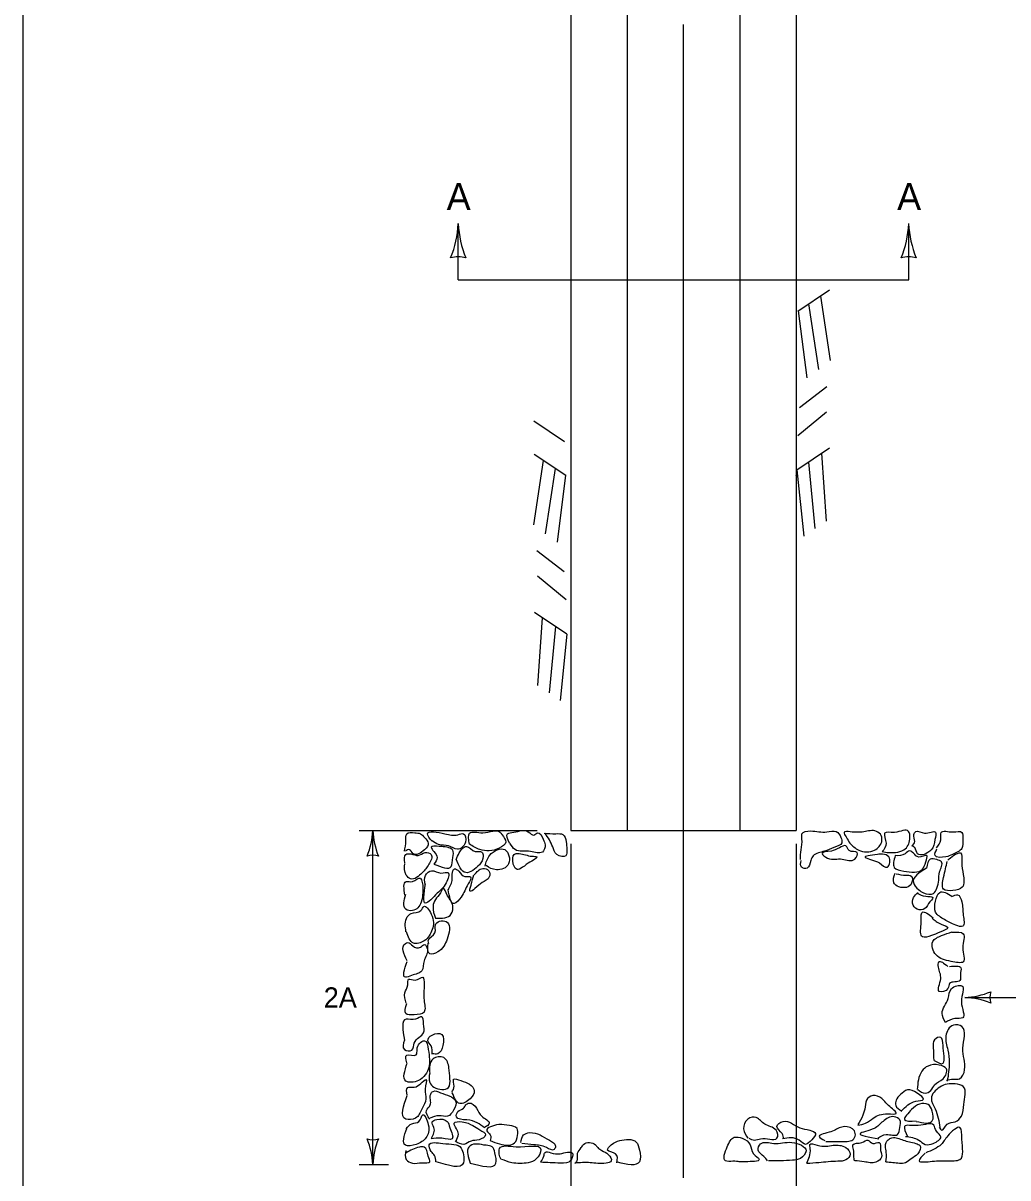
# Model space of a CAD drawing. Extents: x 49991.4 to 50021, y 49987.6 to 50011.4.
# Drawn here: x 50008.067 to 50010.982, y 49993.01 to 49996.429 of the extents above; entities that cross this region are included whole.
import ezdxf

# ---------------------------------------------------------------- set-up
doc = ezdxf.new("R2010")
doc.units = 0
for name, color, linetype in [('Level 1', 7, 'Continuous'), ('Level 2', 7, 'Continuous'), ('Level 3', 7, 'Continuous'), ('Level 6', 7, 'Continuous')]:
    doc.layers.add(name, color=color, linetype=linetype)

msp = doc.modelspace()

# ---------------------------------------------------------------- linework, layer by layer
at = {"layer": 'Level 1'}
for p, q in [((50008.0668, 49990.5622), (50008.0668, 49998.9992)), ((50009.8552, 49997.6503), (50009.8552, 49994.0392)), ((50010.1886, 49997.6503), (50010.1886, 49994.0392)), ((50009.6885, 49997.2058), (50009.6885, 49994.0392)), ((50010.3553, 49997.2058), (50010.3553, 49994.0392)), ((50010.3607, 49995.5769), (50010.4547, 49995.6394)), ((50010.4276, 49995.6214), (50010.4566, 49995.4306)), ((50010.3923, 49995.598), (50010.4218, 49995.4042)), ((50010.3619, 49995.5777), (50010.3872, 49995.3793)), ((50010.3655, 49995.2916), (50010.4466, 49995.3536)), ((50010.3603, 49995.2086), (50010.445, 49995.2788)), ((50009.6701, 49995.1899), (50009.5787, 49995.2511)), ((50009.6739, 49995.09), (50009.5799, 49995.1525)), ((50010.3577, 49995.107), (50010.4541, 49995.1716)), ((50010.4305, 49995.1558), (50010.4444, 49994.9551)), ((50009.6069, 49995.1345), (50009.578, 49994.9438)), ((50009.6422, 49995.111), (50009.6128, 49994.9174)), ((50010.3577, 49995.107), (50010.3781, 49994.9107)), ((50010.3918, 49995.1298), (50010.4107, 49994.933)), ((50009.6728, 49995.0907), (50009.6475, 49994.8924)), ((50009.6691, 49994.8047), (50009.5881, 49994.8668)), ((50009.6743, 49994.7218), (50009.5896, 49994.7919)), ((50009.6768, 49994.6201), (50009.5805, 49994.6847)), ((50009.604, 49994.6689), (50009.5902, 49994.4682)), ((50009.6427, 49994.6429), (50009.6239, 49994.4462)), ((50009.6768, 49994.6201), (50009.6565, 49994.4238)), ((50009.6885, 49994.0392), (50010.3553, 49994.0392))]:
    msp.add_line(p, q, dxfattribs=at)
msp.add_lwpolyline([(50010.3553, 49995.0904), (50010.3537, 49995.089)], dxfattribs=at)
for points in [[(50009.3874, 49994.0005), (50009.3888, 49994.0311), (50009.4277, 49994.0325), (50009.4791, 49994.0339), (50009.4846, 49994.0269), (50009.4957, 49994.0047), (50009.4763, 49993.9866), (50009.4193, 49993.9825), (50009.3874, 49993.9991)], [(50010.6106, 49993.9765), (50010.6217, 49994.0015), (50010.6175, 49994.0307), (50010.6467, 49994.0335), (50010.6884, 49994.0363), (50010.6925, 49994.0182), (50010.6787, 49993.9849), (50010.63, 49993.9738), (50010.6106, 49993.9765)], [(50009.1957, 49993.978), (50009.1998, 49994.0086), (50009.2026, 49994.0294), (50009.2262, 49994.0322), (50009.2429, 49994.0294), (50009.2554, 49994.0183), (50009.2665, 49994.0016), (50009.2554, 49993.9821), (50009.2207, 49993.971), (50009.211, 49993.9821), (50009.1985, 49993.978)], [(50009.2776, 49994.0072), (50009.2637, 49994.0294), (50009.3151, 49994.0294), (50009.354, 49994.0266), (50009.3707, 49994.0294), (50009.3763, 49994.0044), (50009.3526, 49993.9835), (50009.3263, 49993.9933), (50009.2971, 49993.9974), (50009.2776, 49994.0086)], [(50009.5069, 49994.0017), (50009.5013, 49994.0295), (50009.5194, 49994.0337), (50009.5624, 49994.0351), (50009.5791, 49994.0254), (50009.5902, 49994.0323), (50009.6069, 49994.0129), (50009.6124, 49993.9962), (50009.6041, 49993.9753), (50009.5694, 49993.9767), (50009.5235, 49993.9823), (50009.5082, 49994.0017)], [(50009.6097, 49994.0309), (50009.6444, 49994.0295), (50009.6652, 49994.0267), (50009.6749, 49994.0059), (50009.6763, 49993.9823), (50009.6736, 49993.9642), (50009.6472, 49993.9684), (50009.6347, 49993.9906), (50009.6249, 49994.0115), (50009.6124, 49994.0309)], [(50010.3685, 49993.9527), (50010.3699, 49993.9819), (50010.3727, 49994.0139), (50010.3727, 49994.0291), (50010.3977, 49994.0375), (50010.4463, 49994.0347), (50010.4741, 49994.0361), (50010.488, 49994.018), (50010.4907, 49994.0027), (50010.4671, 49993.9888), (50010.4393, 49993.9777), (50010.406, 49993.9638), (50010.399, 49993.95), (50010.3879, 49993.9277), (50010.3713, 49993.9305), (50010.3699, 49993.95)], [(50010.5142, 49994.0018), (50010.5031, 49994.0198), (50010.4976, 49994.0337), (50010.5156, 49994.0351), (50010.5559, 49994.0351), (50010.5934, 49994.0365), (50010.6073, 49994.024), (50010.6087, 49994.0059), (50010.5879, 49993.9809), (50010.5407, 49993.9809), (50010.5142, 49994.0018)], [(50010.6984, 49993.9925), (50010.7067, 49994.0064), (50010.704, 49994.0272), (50010.7095, 49994.0356), (50010.7359, 49994.0314), (50010.7678, 49994.0342), (50010.7665, 49994.012), (50010.7553, 49993.9814), (50010.7151, 49993.9703), (50010.7067, 49993.9883), (50010.6984, 49993.9939)], [(50010.771, 49993.9874), (50010.7836, 49994.0111), (50010.7849, 49994.0333), (50010.8197, 49994.0347), (50010.8461, 49994.0333), (50010.8488, 49994.0139), (50010.8461, 49993.9861), (50010.8183, 49993.968), (50010.7988, 49993.9611), (50010.7669, 49993.9652), (50010.7724, 49993.9847)], [(50009.2832, 49993.9392), (50009.2929, 49993.9587), (50009.2832, 49993.9767), (50009.2749, 49993.9892), (50009.2985, 49993.992), (50009.3221, 49993.9892), (50009.3388, 49993.9809), (50009.3388, 49993.9587), (50009.3346, 49993.9323), (50009.2832, 49993.9392)], [(50009.3485, 49993.9531), (50009.3582, 49993.9726), (50009.3666, 49993.9851), (50009.3791, 49993.992), (50009.4054, 49993.9767), (50009.4249, 49993.9753), (50009.4291, 49993.9628), (50009.4179, 49993.9378), (50009.3777, 49993.9142), (50009.3485, 49993.9545)], [(50009.4346, 49993.9337), (50009.4485, 49993.9656), (50009.493, 49993.9823), (50009.5041, 49993.9406), (50009.468, 49993.9225), (50009.4374, 49993.9351)], [(50010.4599, 49993.978), (50010.4835, 49993.9877), (50010.5029, 49993.9932), (50010.5126, 49993.9794), (50010.5363, 49993.9738), (50010.5293, 49993.9544), (50010.4918, 49993.9544), (50010.4488, 49993.9571), (50010.4321, 49993.971), (50010.4599, 49993.978)], [(50010.6489, 49993.9645), (50010.6781, 49993.9701), (50010.6919, 49993.9784), (50010.7031, 49993.9715), (50010.7183, 49993.9604), (50010.742, 49993.9645), (50010.7392, 49993.9465), (50010.7295, 49993.9243), (50010.6739, 49993.9187), (50010.6461, 49993.9298), (50010.6489, 49993.9645)], [(50009.1971, 49993.9431), (50009.1998, 49993.9681), (50009.2151, 49993.9695), (50009.236, 49993.9653), (50009.2568, 49993.9736), (50009.2749, 49993.9681), (50009.2679, 49993.9389), (50009.2485, 49993.9139), (50009.2137, 49993.8958), (50009.2012, 49993.907), (50009.1971, 49993.9417)], [(50009.518, 49993.9406), (50009.5207, 49993.9684), (50009.5541, 49993.967), (50009.5735, 49993.9628), (50009.5874, 49993.9614), (50009.5624, 49993.942), (50009.5263, 49993.9253), (50009.518, 49993.9392)], [(50010.5963, 49993.9678), (50010.6116, 49993.9692), (50010.6297, 49993.9609), (50010.6324, 49993.9442), (50010.6255, 49993.9303), (50010.6019, 49993.9428), (50010.5783, 49993.9525), (50010.5602, 49993.9595), (50010.5963, 49993.9678)], [(50010.7414, 49993.9278), (50010.7525, 49993.9542), (50010.7719, 49993.9528), (50010.7858, 49993.9459), (50010.7803, 49993.9167), (50010.7775, 49993.8917), (50010.7719, 49993.8681), (50010.7622, 49993.8528), (50010.733, 49993.8542), (50010.7177, 49993.8639), (50010.7025, 49993.8848), (50010.7414, 49993.9278)], [(50010.8044, 49993.9516), (50010.8224, 49993.9655), (50010.8419, 49993.9724), (50010.8461, 49993.946), (50010.8502, 49993.9085), (50010.8474, 49993.871), (50010.8197, 49993.8613), (50010.7919, 49993.8655), (50010.7919, 49993.9002), (50010.803, 49993.9474)], [(50009.2568, 49993.8795), (50009.2582, 49993.9059), (50009.2762, 49993.9198), (50009.304, 49993.9128), (50009.3249, 49993.9142), (50009.3193, 49993.8837), (50009.2929, 49993.8531), (50009.2582, 49993.8239), (50009.2582, 49993.8809)], [(50009.3249, 49993.8628), (50009.3374, 49993.8948), (50009.3374, 49993.91), (50009.3443, 49993.9253), (50009.3568, 49993.9184), (50009.3749, 49993.9031), (50009.3916, 49993.9017), (50009.3846, 49993.8809), (50009.3638, 49993.842), (50009.3429, 49993.8225), (50009.3249, 49993.8642)], [(50009.4027, 49993.9073), (50009.4277, 49993.9267), (50009.4457, 49993.9198), (50009.4471, 49993.9017), (50009.4263, 49993.885), (50009.4041, 49993.867), (50009.3902, 49993.8587), (50009.3929, 49993.8767), (50009.4013, 49993.9073)], [(50010.6516, 49993.9109), (50010.6807, 49993.9067), (50010.696, 49993.9039), (50010.6974, 49993.8831), (50010.6821, 49993.8706), (50010.6446, 49993.8845), (50010.6488, 49993.9123)], [(50009.1971, 49993.8475), (50009.2012, 49993.8878), (50009.2193, 49993.8878), (50009.2429, 49993.8975), (50009.2485, 49993.885), (50009.2499, 49993.8545), (50009.2457, 49993.8267), (50009.2193, 49993.8017), (50009.1998, 49993.8059), (50009.1998, 49993.8503)], [(50009.2874, 49993.7793), (50009.2804, 49993.814), (50009.2874, 49993.8349), (50009.3026, 49993.8543), (50009.3096, 49993.8682), (50009.3235, 49993.846), (50009.3388, 49993.8168), (50009.3346, 49993.7918), (50009.2874, 49993.7793)], [(50010.7141, 49993.853), (50010.7391, 49993.8446), (50010.7599, 49993.8404), (50010.7474, 49993.8224), (50010.7405, 49993.8113), (50010.7196, 49993.8043), (50010.7016, 49993.8182), (50010.703, 49993.8404), (50010.7169, 49993.8557)], [(50010.8169, 49993.8432), (50010.8336, 49993.8488), (50010.8461, 49993.8279), (50010.8502, 49993.7877), (50010.8488, 49993.7557), (50010.828, 49993.7585), (50010.7947, 49993.7752), (50010.7683, 49993.7974), (50010.7683, 49993.8293), (50010.7808, 49993.8557), (50010.8169, 49993.8446)], [(50009.2002, 49993.7387), (50009.2043, 49993.7832), (50009.2155, 49993.7929), (50009.2446, 49993.8026), (50009.253, 49993.8137), (50009.2752, 49993.7915), (50009.278, 49993.7456), (50009.2543, 49993.7123), (50009.2224, 49993.7054), (50009.2016, 49993.7387)], [(50009.2679, 49993.7043), (50009.2665, 49993.7126), (50009.286, 49993.7362), (50009.2888, 49993.7626), (50009.3235, 49993.7668), (50009.329, 49993.746), (50009.3221, 49993.7168), (50009.2943, 49993.6793), (50009.2707, 49993.6737), (50009.2665, 49993.7057)], [(50010.7585, 49993.7793), (50010.7849, 49993.7612), (50010.8044, 49993.7515), (50010.7808, 49993.7376), (50010.7558, 49993.7279), (50010.7294, 49993.7237), (50010.7252, 49993.7612), (50010.7294, 49993.7974), (50010.7613, 49993.7807)], [(50010.8169, 49993.7376), (50010.8502, 49993.7335), (50010.8488, 49993.6918), (50010.8502, 49993.6501), (50010.8141, 49993.6515), (50010.7696, 49993.6709), (50010.7599, 49993.7099), (50010.7863, 49993.7279), (50010.8169, 49993.739)], [(50009.204, 49993.6529), (50009.1985, 49993.7043), (50009.2054, 49993.7071), (50009.2207, 49993.6974), (50009.2429, 49993.6932), (50009.2554, 49993.7015), (50009.2637, 49993.6876), (50009.254, 49993.6529), (50009.2471, 49993.6237), (50009.2165, 49993.6098), (50009.1985, 49993.6043), (50009.204, 49993.6515)], [(50010.8099, 49993.6362), (50010.8433, 49993.6321), (50010.8419, 49993.6126), (50010.8405, 49993.5945), (50010.8099, 49993.5862), (50010.8044, 49993.5709), (50010.7794, 49993.5626), (50010.7836, 49993.6001), (50010.7766, 49993.6348), (50010.778, 49993.6501), (50010.8044, 49993.6362)], [(50009.2012, 49993.5279), (50009.1971, 49993.5584), (50009.2054, 49993.582), (50009.2082, 49993.5987), (50009.2276, 49993.5959), (50009.2499, 49993.6043), (50009.254, 49993.5848), (50009.254, 49993.5362), (50009.254, 49993.5015), (50009.2249, 49993.4931), (50009.1998, 49993.4973), (50009.2026, 49993.5265)], [(50010.7974, 49993.4709), (50010.8252, 49993.482), (50010.8488, 49993.4848), (50010.8447, 49993.532), (50010.8461, 49993.5793), (50010.8155, 49993.5709), (50010.8058, 49993.5418), (50010.7877, 49993.4973), (50010.7974, 49993.4709)], [(50009.1957, 49993.4181), (50009.2012, 49993.4806), (50009.229, 49993.4806), (50009.2471, 49993.4876), (50009.2526, 49993.4667), (50009.2526, 49993.4404), (50009.2249, 49993.4098), (50009.2179, 49993.3889), (50009.1957, 49993.3903), (50009.1957, 49993.4181)], [(50010.8002, 49993.3), (50010.8211, 49993.3028), (50010.8391, 49993.3042), (50010.8544, 49993.3306), (50010.8488, 49993.3945), (50010.8461, 49993.4584), (50010.8211, 49993.4626), (50010.7988, 49993.4306), (50010.8044, 49993.3889), (50010.8086, 49993.3514), (50010.803, 49993.2973)], [(50009.2776, 49993.3764), (50009.2749, 49993.4014), (50009.2651, 49993.4167), (50009.2776, 49993.4334), (50009.3068, 49993.4348), (50009.3096, 49993.4028), (50009.2943, 49993.3778), (50009.279, 49993.3778)], [(50009.2026, 49993.3514), (50009.2026, 49993.3737), (50009.2304, 49993.3751), (50009.2332, 49993.3903), (50009.2401, 49993.4084), (50009.2554, 49993.4167), (50009.2665, 49993.3903), (50009.2679, 49993.3375), (50009.2374, 49993.2986), (50009.1998, 49993.2973), (50009.204, 49993.3501)], [(50010.7641, 49993.3584), (50010.7905, 49993.3501), (50010.7933, 49993.3709), (50010.7905, 49993.4028), (50010.7836, 49993.4264), (50010.7655, 49993.4195), (50010.7613, 49993.3959), (50010.7627, 49993.3584)], [(50009.2707, 49993.3209), (50009.2707, 49993.2931), (50009.2832, 49993.2792), (50009.3068, 49993.2723), (50009.3263, 49993.2778), (50009.3304, 49993.3042), (50009.3276, 49993.3361), (50009.3124, 49993.3667), (50009.2804, 49993.3626), (50009.2707, 49993.3195)], [(50010.7155, 49993.2723), (50010.7377, 49993.2611), (50010.7544, 49993.2695), (50010.7655, 49993.2861), (50010.7905, 49993.3042), (50010.8002, 49993.3334), (50010.7794, 49993.3445), (50010.746, 49993.3417), (50010.728, 49993.3264), (50010.7141, 49993.2723)], [(50009.204, 49993.2556), (50009.2054, 49993.2778), (50009.2249, 49993.2792), (50009.2443, 49993.2903), (50009.2596, 49993.3014), (50009.2568, 49993.2736), (50009.2596, 49993.2445), (50009.2471, 49993.2139), (50009.229, 49993.1875), (50009.1998, 49993.1847), (50009.204, 49993.2542)], [(50009.336, 49993.2639), (50009.3429, 49993.282), (50009.3415, 49993.3028), (50009.3624, 49993.2986), (50009.3888, 49993.2875), (50009.4027, 49993.2681), (50009.3902, 49993.2445), (50009.3596, 49993.2306), (50009.3374, 49993.2625)], [(50009.2707, 49993.1847), (50009.261, 49993.2097), (50009.2721, 49993.2264), (50009.2735, 49993.2584), (50009.2804, 49993.2667), (50009.3026, 49993.2625), (50009.3304, 49993.2528), (50009.3471, 49993.2389), (50009.3415, 49993.2111), (50009.3235, 49993.1931), (50009.2985, 49993.1945), (50009.2721, 49993.1875)], [(50010.6669, 49993.2084), (50010.6863, 49993.2264), (50010.7099, 49993.2375), (50010.7321, 49993.2431), (50010.7141, 49993.2611), (50010.6849, 49993.2709), (50010.6641, 49993.257), (50010.6516, 49993.2403), (50010.6502, 49993.225), (50010.6682, 49993.2084)], [(50010.7794, 49993.1611), (50010.7863, 49993.1514), (50010.803, 49993.1694), (50010.8266, 49993.1764), (50010.8447, 49993.1931), (50010.8516, 49993.2278), (50010.8502, 49993.2806), (50010.8266, 49993.2889), (50010.7808, 49993.2792), (50010.7558, 49993.2459), (50010.7669, 49993.2153), (50010.7808, 49993.1597)], [(50009.4332, 49993.1583), (50009.411, 49993.1736), (50009.3804, 49993.182), (50009.3499, 49993.1917), (50009.354, 49993.207), (50009.3707, 49993.2167), (50009.3777, 49993.2264), (50009.3874, 49993.232), (50009.4096, 49993.2167), (50009.4249, 49993.1931), (50009.4471, 49993.1722), (50009.4332, 49993.1597)], [(50010.5377, 49993.1667), (50010.5613, 49993.1722), (50010.5835, 49993.1875), (50010.6266, 49993.2), (50010.6516, 49993.2014), (50010.6293, 49993.225), (50010.6141, 49993.2403), (50010.5891, 49993.2542), (50010.5668, 49993.2459), (50010.5599, 49993.2209), (50010.5529, 49993.1958), (50010.5377, 49993.1681)], [(50010.7113, 49993.1778), (50010.7585, 49993.1792), (50010.7585, 49993.2084), (50010.746, 49993.2278), (50010.721, 49993.2292), (50010.6974, 49993.2125), (50010.6766, 49993.1833), (50010.7113, 49993.1792)], [(50009.2012, 49993.1556), (50009.2179, 49993.1708), (50009.2387, 49993.1778), (50009.2499, 49993.1972), (50009.2665, 49993.1681), (50009.2596, 49993.1292), (50009.2304, 49993.1097), (50009.1985, 49993.1069), (50009.2026, 49993.1569)], [(50010.2154, 49993.1278), (50010.232, 49993.1222), (50010.2501, 49993.1264), (50010.2779, 49993.125), (50010.2987, 49993.1278), (50010.2959, 49993.1514), (50010.2626, 49993.1694), (50010.2376, 49993.1889), (50010.2126, 49993.1847), (50010.2001, 49993.1556), (50010.2126, 49993.1278)], [(50010.5974, 49993.1278), (50010.6224, 49993.1389), (50010.6557, 49993.1389), (50010.6627, 49993.1597), (50010.6627, 49993.182), (50010.646, 49993.1917), (50010.6127, 49993.1778), (50010.5863, 49993.1569), (50010.5446, 49993.1417), (50010.6002, 49993.1264)], [(50009.2762, 49993.1278), (50009.2832, 49993.1597), (50009.2776, 49993.1764), (50009.2915, 49993.1833), (50009.3221, 49993.1778), (50009.3304, 49993.1583), (50009.3374, 49993.1264), (50009.3068, 49993.1278), (50009.2749, 49993.1264)], [(50009.3485, 49993.1194), (50009.3554, 49993.1403), (50009.3499, 49993.1556), (50009.3429, 49993.1722), (50009.3666, 49993.1764), (50009.3985, 49993.1653), (50009.4193, 49993.1528), (50009.436, 49993.1375), (50009.4166, 49993.1236), (50009.3929, 49993.1194), (50009.3721, 49993.1097), (50009.3457, 49993.1194)], [(50009.4499, 49993.1208), (50009.4499, 49993.1375), (50009.4402, 49993.15), (50009.4749, 49993.1681), (50009.5069, 49993.1653), (50009.5291, 49993.1569), (50009.5305, 49993.1361), (50009.5221, 49993.1139), (50009.4777, 49993.1111), (50009.4499, 49993.1208)], [(50010.3182, 49993.1264), (50010.314, 49993.1417), (50010.2987, 49993.1625), (50010.3168, 49993.1778), (50010.3418, 49993.1722), (50010.3668, 49993.1583), (50010.396, 49993.1514), (50010.4126, 49993.1417), (50010.4015, 49993.1236), (50010.3835, 49993.1097), (50010.364, 49993.1222), (50010.3154, 49993.1264)], [(50010.4432, 49993.1181), (50010.4918, 49993.1181), (50010.5265, 49993.1264), (50010.5307, 49993.1417), (50010.5224, 49993.1556), (50010.4904, 49993.1611), (50010.4585, 49993.1472), (50010.4237, 49993.1333), (50010.4404, 49993.1208)], [(50010.6794, 49993.1333), (50010.7183, 49993.1222), (50010.7377, 49993.1097), (50010.7613, 49993.1125), (50010.7836, 49993.1319), (50010.771, 49993.1486), (50010.7627, 49993.1667), (50010.7169, 49993.1653), (50010.6766, 49993.1625), (50010.6849, 49993.1333)], [(50010.7377, 49993.0833), (50010.7196, 49993.0611), (50010.7585, 49993.0597), (50010.803, 49993.0611), (50010.8405, 49993.0653), (50010.8461, 49993.125), (50010.8405, 49993.1597), (50010.8044, 49993.1347), (50010.7849, 49993.1097), (50010.7391, 49993.0847)], [(50009.5402, 49993.1153), (50009.5485, 49993.1375), (50009.5666, 49993.1444), (50009.5972, 49993.1375), (50009.6249, 49993.1222), (50009.643, 49993.1042), (50009.6388, 49993.0944), (50009.6166, 49993.1), (50009.5791, 49993.1083), (50009.543, 49993.1125)], [(50009.825, 49993.0555), (50009.8208, 49993.0819), (50009.7972, 49993.093), (50009.8083, 49993.1083), (50009.8333, 49993.1208), (50009.882, 49993.1167), (50009.8917, 49993.093), (50009.8917, 49993.0583), (50009.8264, 49993.0569)], [(50010.189, 49993.0583), (50010.1681, 49993.0597), (50010.1459, 49993.0611), (50010.1515, 49993.1028), (50010.1723, 49993.1306), (50010.1959, 49993.1278), (50010.2195, 49993.1083), (50010.2293, 49993.0819), (50010.2459, 49993.0653), (50010.2056, 49993.0583), (50010.1862, 49993.0583)], [(50010.5279, 49993.0611), (50010.5265, 49993.075), (50010.5251, 49993.0944), (50010.5238, 49993.1083), (50010.5502, 49993.1153), (50010.5682, 49993.1222), (50010.5821, 49993.1125), (50010.6016, 49993.1153), (50010.6057, 49993.0916), (50010.6085, 49993.0722), (50010.5918, 49993.0569), (50010.5571, 49993.0583), (50010.5293, 49993.0611)], [(50010.621, 49993.0583), (50010.6224, 49993.0861), (50010.6196, 49993.1042), (50010.628, 49993.1236), (50010.6391, 49993.1292), (50010.6724, 49993.1222), (50010.7099, 49993.1125), (50010.7224, 49993.1056), (50010.7155, 49993.0819), (50010.696, 49993.0666), (50010.6794, 49993.0555), (50010.6418, 49993.0555), (50010.621, 49993.0569)], [(50009.1998, 49993.0916), (50009.2012, 49993.0653), (50009.2193, 49993.0541), (50009.2485, 49993.0555), (50009.2707, 49993.0583), (50009.2665, 49993.075), (50009.254, 49993.1014), (50009.2401, 49993.1014), (50009.2012, 49993.0847)], [(50009.2888, 49993.0583), (50009.2846, 49993.0764), (50009.2749, 49993.0889), (50009.2693, 49993.1083), (50009.3096, 49993.1125), (50009.3638, 49993.0986), (50009.3707, 49993.0791), (50009.3707, 49993.0555), (50009.2901, 49993.0583)], [(50009.3902, 49993.0541), (50009.3832, 49993.0805), (50009.3832, 49993.0958), (50009.3902, 49993.1056), (50009.4374, 49993.1069), (50009.4555, 49993.1028), (50009.4638, 49993.0847), (50009.4666, 49993.0541), (50009.3902, 49993.0541)], [(50009.4819, 49993.0653), (50009.4763, 49993.0805), (50009.4777, 49993.0972), (50009.5263, 49993.1028), (50009.5999, 49993.0944), (50009.586, 49993.0666), (50009.5624, 49993.0555), (50009.5138, 49993.0555), (50009.4832, 49993.0653)], [(50009.5999, 49993.0583), (50009.6083, 49993.075), (50009.6124, 49993.0861), (50009.6291, 49993.0847), (50009.6569, 49993.0819), (50009.693, 49993.0833), (50009.6888, 49993.0625), (50009.6583, 49993.0541), (50009.5985, 49993.0569)], [(50009.7, 49993.0528), (50009.7069, 49993.0611), (50009.7083, 49993.0833), (50009.7194, 49993.1), (50009.7264, 49993.1097), (50009.7611, 49993.1083), (50009.768, 49993.1), (50009.7805, 49993.0916), (50009.8, 49993.0791), (50009.8083, 49993.0611), (50009.793, 49993.0541), (50009.7458, 49993.0555), (50009.7, 49993.0541)], [(50010.2709, 49993.0611), (50010.2598, 49993.0736), (50010.2431, 49993.093), (50010.2501, 49993.1111), (50010.289, 49993.1125), (50010.3432, 49993.1153), (50010.3848, 49993.0903), (50010.3682, 49993.068), (50010.3446, 49993.0625), (50010.2737, 49993.0611)], [(50010.3876, 49993.0541), (50010.3946, 49993.0736), (50010.3973, 49993.0972), (50010.396, 49993.1097), (50010.4182, 49993.1069), (50010.4654, 49993.1069), (50010.5029, 49993.1), (50010.5154, 49993.0805), (50010.5029, 49993.0639), (50010.4793, 49993.0597), (50010.4223, 49993.0555), (50010.3876, 49993.0528)]]:
    msp.add_spline(points, degree=3, dxfattribs=at)
at = {"layer": 'Level 3'}
for p, q in [((50009.0622, 49994.0392), (50009.5885, 49994.0392)), ((50009.1022, 49993.0499), (50009.1022, 49994.0392)), ((50009.6885, 49993.9992), (50009.6885, 49992.8309)), ((50010.3553, 49993.9992), (50010.3553, 49992.8309)), ((50010.8554, 49993.5446), (50011.0288, 49993.5446)), ((50009.0622, 49993.0499), (50009.1484, 49993.0499))]:
    msp.add_line(p, q, dxfattribs=at)
for centre, radius, start, end in [((50008.88, 49994.0484), 0.2223, 337.456, 357.6395), ((50009.3349, 49994.0507), 0.233, 182.8273, 202.0772), ((50009.1022, 49993.911), 0.0548, 72.1388, 107.8612), ((50010.8439, 49993.7773), 0.233, 272.8273, 292.0772), ((50010.8462, 49993.3224), 0.2223, 67.456, 87.6395), ((50010.9836, 49993.5446), 0.0548, 162.1388, 197.8612), ((50009.1022, 49993.1781), 0.0548, 252.1388, 287.8612), ((50008.8694, 49993.0384), 0.233, 2.8273, 22.0772), ((50009.3243, 49993.0408), 0.2223, 157.456, 177.6395)]:
    msp.add_arc(centre, radius, start, end, dxfattribs=at)
at = {"layer": 'Level 6'}
for p, q in [((50010.0219, 49993.0109), (50010.0219, 49996.4249)), ((50009.3551, 49995.669), (50009.3551, 49995.8357)), ((50010.6887, 49995.669), (50010.6887, 49995.8357)), ((50009.3551, 49995.669), (50010.6887, 49995.669))]:
    msp.add_line(p, q, dxfattribs=at)
for centre, radius, start, end in [((50009.0589, 49995.8479), 0.2964, 337.456, 357.6395), ((50009.6653, 49995.851), 0.3107, 182.8273, 202.0772), ((50010.3925, 49995.8479), 0.2964, 337.456, 357.6395), ((50010.9989, 49995.851), 0.3107, 182.8273, 202.0772), ((50009.3551, 49995.6648), 0.073, 72.1388, 107.8612), ((50010.6887, 49995.6648), 0.073, 72.1388, 107.8612)]:
    msp.add_arc(centre, radius, start, end, dxfattribs=at)

# ---------------------------------------------------------------- texts
at = {"layer": 'Level 2'}
for s, height, p in [('A', 0.08, (50009.3207, 49995.8757)), ('A', 0.08, (50010.6543, 49995.8757)), ('2A', 0.06, (50008.9568, 49993.5146))]:
    msp.add_text(s, height=height, dxfattribs=at).set_placement(p)

doc.saveas('drawing.dxf')
